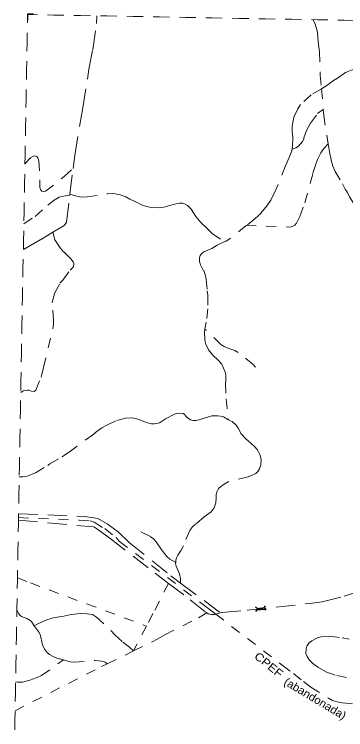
# Model space of a CAD drawing. Extents: x 783.4 to 809.8, y 7536.4 to 7564.6.
# Drawn here: x 783.82 to 787.12, y 7557.44 to 7564.59 of the extents above; entities that cross this region are included whole.
import ezdxf
from ezdxf.enums import TextEntityAlignment as Align

# ---------------------------------------------------------------- set-up
doc = ezdxf.new("R2010")
doc.units = 0
doc.header["$LTSCALE"] = 0.032
for name, pattern in [('DOTTED', [1.5, 0.3, -1.2]), ('LONG_DASHED', [7.5, 6, -1.5]), ('MEDIUM_DASHED', [4.5, 3, -1.5]), ('SHORT_DASHED', [2.7, 1.5, -1.2])]:
    doc.linetypes.add(name, pattern=pattern)
for name, color, linetype, lineweight in [('10', 7, 'Continuous', 25), ('18', 7, 'DOTTED', 13), ('35', 7, 'SHORT_DASHED', 13), ('5', 7, 'LONG_DASHED', 13), ('6', 7, 'MEDIUM_DASHED', 13), ('63', 7, 'Continuous', 25), ('7', 7, 'DOTTED', 13)]:
    doc.layers.add(name, color=color, linetype=linetype, lineweight=lineweight)
doc.layers.add('61', color=7, linetype='Continuous')

msp = doc.modelspace()

# ---------------------------------------------------------------- linework, layer by layer
at = {"layer": '10'}
for p, q in [((786.2398, 7558.6539), (786.2243, 7558.6664)), ((786.2293, 7558.6224), (786.2416, 7558.638)), ((786.2416, 7558.638), (786.3151, 7558.6464)), ((786.3308, 7558.634), (786.3151, 7558.6464))]:
    msp.add_line(p, q, dxfattribs=at)
msp.add_lwpolyline([(786.2398, 7558.6539), (786.3133, 7558.6623), (786.3258, 7558.6779)], dxfattribs=at)
at = {"layer": '18'}
for points in [[(783.8574, 7559.56), (784.463, 7559.5355), (784.5715, 7559.528), (784.6117, 7559.5148), (784.7183, 7559.4507), (784.8325, 7559.3604), (784.8676, 7559.3228), (785.7496, 7558.6555), (785.8274, 7558.5958)], [(785.8274, 7558.5958), (786.4912, 7558.086), (786.6044, 7558.0024), (786.7026, 7557.9216), (786.7781, 7557.8648), (786.9545, 7557.7548), (786.9946, 7557.7341), (787.0407, 7557.7191), (787.0948, 7557.7088), (787.2035, 7557.6979)], [(787.1334, 7557.962), (787.0201, 7557.9846), (786.9229, 7558.0221), (786.8462, 7558.0649), (786.7971, 7558.1043), (786.7641, 7558.1353), (786.74, 7558.172), (786.728, 7558.203), (786.73, 7558.249), (786.737, 7558.2772), (786.758, 7558.3054), (786.7861, 7558.3308), (786.8427, 7558.3594), (786.8788, 7558.3679), (786.9639, 7558.3745), (787.0882, 7558.3594), (787.1604, 7558.3472)]]:
    msp.add_lwpolyline(points, dxfattribs=at)
at = {"layer": '35'}
for points in [[(783.8156, 7557.2399), (783.8207, 7557.5225), (783.8258, 7557.8051), (783.8309, 7558.0877), (783.836, 7558.3703), (783.8411, 7558.6529), (783.8462, 7558.9355), (783.8513, 7559.2181), (783.8563, 7559.5007), (783.8614, 7559.7833), (783.8665, 7560.0659), (783.8716, 7560.3486), (783.8767, 7560.6312), (783.8818, 7560.9138), (783.8869, 7561.1964), (783.892, 7561.479), (783.8971, 7561.7616), (783.9022, 7562.0442), (783.9073, 7562.3268), (783.9124, 7562.6094), (783.9175, 7562.892), (783.9226, 7563.1746), (783.9276, 7563.4572), (783.9327, 7563.7398), (783.9378, 7564.0224), (783.9429, 7564.305), (783.948, 7564.5876)], [(783.948, 7564.5876), (784.2116, 7564.5828), (784.4751, 7564.5781), (784.7386, 7564.5734), (785.0022, 7564.5686), (785.2658, 7564.5638), (785.5293, 7564.5591), (785.7928, 7564.5543), (786.0564, 7564.5495), (786.32, 7564.5448), (786.5835, 7564.54), (786.8471, 7564.5352), (787.1106, 7564.5304), (787.3742, 7564.5256)]]:
    msp.add_lwpolyline(points, dxfattribs=at)
at = {"layer": '5'}
for p, q in [((784.3707, 7562.7919), (784.4023, 7563.0493)), ((784.369, 7562.7827), (784.3707, 7562.7919)), ((785.4768, 7558.9053), (785.8748, 7558.6082)), ((785.8274, 7558.5958), (785.8748, 7558.6082))]:
    msp.add_line(p, q, dxfattribs=at)
for points in [[(784.4023, 7563.0493), (784.4186, 7563.1803), (784.5004, 7563.6546), (784.5611, 7564.0414), (784.5988, 7564.2362), (784.6364, 7564.4979), (784.6384, 7564.5752)], [(784.1997, 7562.412), (784.3142, 7562.4811), (784.3282, 7562.4962), (784.3352, 7562.5112), (784.369, 7562.7827)], [(783.9057, 7562.2394), (784.0761, 7562.3374), (784.1997, 7562.412)], [(783.8581, 7559.5989), (784.5147, 7559.572), (784.5909, 7559.5622), (784.6454, 7559.5517), (784.6746, 7559.5398), (784.7422, 7559.4968), (784.8512, 7559.4169), (784.964, 7559.3105), (785.3785, 7558.9787), (785.4768, 7558.9053)], [(783.8569, 7559.5339), (784.6038, 7559.4683), (784.6165, 7559.4636), (784.7709, 7559.3546), (785.2212, 7559.0049), (785.3553, 7558.9033)], [(785.3553, 7558.9033), (785.5704, 7558.7404), (785.7261, 7558.6159), (785.7388, 7558.6078)], [(785.8748, 7558.6082), (785.8857, 7558.6111), (786.1407, 7558.6346), (786.7687, 7558.7026), (786.8889, 7558.7205), (787.1099, 7558.7755), (787.2861, 7558.8329)], [(785.7388, 7558.6078), (785.7524, 7558.5992), (785.7838, 7558.5912), (785.8101, 7558.5912), (785.8274, 7558.5958)]]:
    msp.add_lwpolyline(points, dxfattribs=at)
at = {"layer": '6'}
for p, q in [((786.8831, 7563.8462), (786.9014, 7563.6374)), ((784.742, 7558.0992), (785.0057, 7558.2287))]:
    msp.add_line(p, q, dxfattribs=at)
for points in [[(786.8013, 7564.536), (786.8203, 7564.4916), (786.8426, 7564.4125), (786.849, 7564.314), (786.8649, 7564.214), (786.8713, 7563.9812), (786.8831, 7563.8462)], [(786.9014, 7563.6374), (786.9064, 7563.5801), (786.9495, 7563.2966)], [(786.9495, 7563.2966), (786.9617, 7563.2165), (786.9817, 7563.1205), (786.995, 7563.0718), (787.0184, 7563.02), (787.0928, 7562.8966), (787.1192, 7562.843), (787.144, 7562.8086), (787.1632, 7562.767), (787.2024, 7562.7038), (787.324, 7562.4822), (787.4856, 7562.2054), (787.5128, 7562.1486), (787.583, 7561.9574), (787.609, 7561.8711), (787.6365, 7561.7914)], [(783.88, 7560.8119), (783.9044, 7560.8263), (783.9423, 7560.8343), (783.9594, 7560.8336), (783.988, 7560.8227), (784.0143, 7560.8213), (784.0321, 7560.835), (784.0832, 7560.9649), (784.1086, 7561.0613), (784.199, 7561.4477), (784.2054, 7561.4917), (784.2062, 7561.5349), (784.1942, 7561.7078), (784.2054, 7561.763), (784.2198, 7561.8054), (784.2718, 7561.9022), (784.2998, 7561.9342), (784.3728, 7562.0344), (784.4019, 7562.0627), (784.4099, 7562.0853), (784.4099, 7562.0984), (784.4019, 7562.1163), (784.3808, 7562.1455), (784.3076, 7562.2161), (784.2735, 7562.2565), (784.2188, 7562.3356), (784.1997, 7562.412)], [(785.0057, 7558.2287), (785.2479, 7558.3477), (785.3204, 7558.3904), (785.6548, 7558.5575), (785.7388, 7558.6078)], [(783.8227, 7557.6313), (784.6867, 7558.072), (784.742, 7558.0992)]]:
    msp.add_lwpolyline(points, dxfattribs=at)
at = {"layer": '63'}
msp.add_lwpolyline([(784.0079, 7564.5899), (783.9463, 7564.5899), (783.9463, 7564.5292)], dxfattribs=at)
at = {"layer": '7'}
msp.add_line((785.1349, 7558.4763), (785.0057, 7558.2287), dxfattribs=at)
for points in [[(787.6817, 7563.7279), (787.657, 7563.742), (787.5439, 7563.7739), (787.4766, 7563.8071), (787.4468, 7563.8311), (787.4274, 7563.8513), (787.4114, 7563.8747), (787.3961, 7563.9092), (787.383, 7563.9716), (787.367, 7564.0126), (787.3351, 7564.0458), (787.3219, 7564.0516), (787.2851, 7564.0555), (787.1887, 7564.0347), (787.1225, 7564.0084), (787.0448, 7563.9531), (787.0031, 7563.9286), (786.9359, 7563.8782), (786.8831, 7563.8462)], [(786.8831, 7563.8462), (786.7817, 7563.7846), (786.6751, 7563.6896), (786.6469, 7563.6458), (786.6061, 7563.5616), (786.5898, 7563.4726), (786.5895, 7563.4152), (786.5969, 7563.3644), (786.5947, 7563.267), (786.5901, 7563.2433)], [(786.5901, 7563.2433), (786.6266, 7563.2542), (786.6526, 7563.2716), (786.6951, 7563.3198), (786.7055, 7563.343), (786.7071, 7563.355), (786.7335, 7563.4286), (786.7727, 7563.5022), (786.8443, 7563.5977), (786.8673, 7563.6164), (786.9014, 7563.6374)], [(786.1324, 7562.4779), (786.5616, 7562.4639), (786.583, 7562.466), (786.6172, 7562.484), (786.6354, 7562.502), (786.6675, 7562.5692), (786.7156, 7562.7065), (786.7983, 7563.0041), (786.8265, 7563.0932), (786.8443, 7563.1391), (786.8759, 7563.2062), (786.9063, 7563.2501), (786.9495, 7563.2966)], [(786.5901, 7563.2433), (786.5865, 7563.2246), (786.5617, 7563.1602), (786.5224, 7563.0768), (786.4223, 7562.823), (786.3775, 7562.7342), (786.3423, 7562.6798), (786.2767, 7562.5998), (786.2215, 7562.5486), (786.1324, 7562.4779)], [(783.9212, 7563.0955), (783.9782, 7563.1568), (784.0138, 7563.1766), (784.0416, 7563.168), (784.0495, 7563.1568), (784.0613, 7563.1259), (784.0706, 7562.9342), (784.0693, 7562.8587), (784.0798, 7562.8327), (784.0891, 7562.8241), (784.1102, 7562.8191), (784.1286, 7562.8216), (784.3134, 7562.97), (784.4023, 7563.0493)], [(783.9104, 7562.4975), (784.0231, 7562.5692), (784.1498, 7562.6843), (784.2131, 7562.7325), (784.2619, 7562.761), (784.322, 7562.7762), (784.369, 7562.7827)], [(784.3707, 7562.7919), (784.4282, 7562.7758), (784.4823, 7562.7635), (784.543, 7562.7647), (784.7503, 7562.7966), (784.7959, 7562.7998), (784.8215, 7562.7974), (784.8727, 7562.7862), (784.9287, 7562.7654), (784.9695, 7562.7422), (785.0431, 7562.7094), (785.0871, 7562.6862), (785.1345, 7562.6682), (785.1855, 7562.6582), (785.2687, 7562.655), (785.3207, 7562.6646), (785.4015, 7562.6886), (785.4647, 7562.703), (785.4967, 7562.7022), (785.5167, 7562.6966), (785.5447, 7562.679), (785.5807, 7562.6414), (785.6271, 7562.5678), (785.6767, 7562.5094), (785.7367, 7562.4542), (785.7911, 7562.3998), (785.912, 7562.3156)], [(786.1324, 7562.4779), (785.9761, 7562.3539), (785.9308, 7562.3246), (785.912, 7562.3156)], [(785.912, 7562.3156), (785.8425, 7562.2822), (785.7888, 7562.2512), (785.7086, 7562.2158), (785.6834, 7562.1977), (785.6716, 7562.1782), (785.6656, 7562.1573), (785.6649, 7562.1191), (785.6745, 7562.0878), (785.7031, 7562.0334), (785.7079, 7562.0294), (785.7204, 7561.9909), (785.7308, 7561.9422), (785.7415, 7561.827), (785.7495, 7561.783), (785.7495, 7561.6478), (785.7327, 7561.5125), (785.7198, 7561.4445)], [(785.7198, 7561.4445), (785.7156, 7561.4222), (785.7186, 7561.3332), (785.729, 7561.2942), (785.7557, 7561.2372), (785.794, 7561.1868), (785.8543, 7561.1301), (785.8871, 7561.0925), (785.9207, 7561.0149), (785.9271, 7560.9869), (785.9287, 7560.9205), (785.9255, 7560.9037), (785.9303, 7560.7458), (785.9547, 7560.5392)], [(786.2245, 7561.0651), (786.2019, 7561.0909), (786.0518, 7561.2094), (786.0168, 7561.2317), (785.9592, 7561.2493), (785.9117, 7561.2704), (785.8791, 7561.2915), (785.7198, 7561.4445)], [(783.8647, 7559.9672), (783.9015, 7559.9686), (783.943, 7559.9755), (784.0275, 7560.0096), (784.1502, 7560.0821), (784.171, 7560.0989), (784.2926, 7560.1693), (784.351, 7560.2093), (784.3631, 7560.2141), (784.5983, 7560.3885), (784.6415, 7560.4253), (784.6887, 7560.4581), (784.7399, 7560.4853), (784.8407, 7560.5309), (784.9271, 7560.5549), (784.9943, 7560.5581), (785.0623, 7560.5421), (785.1335, 7560.5101), (785.1863, 7560.4981), (785.2167, 7560.4965), (785.2671, 7560.5077), (785.3271, 7560.5485), (785.4151, 7560.5957), (785.4471, 7560.6045), (785.5055, 7560.6005), (785.5415, 7560.5613), (785.5743, 7560.5373), (785.6023, 7560.5301), (785.6279, 7560.5293), (785.6607, 7560.5373), (785.7127, 7560.5557), (785.7895, 7560.5765), (785.8487, 7560.5789), (785.8743, 7560.5757), (785.9055, 7560.5661), (785.9487, 7560.5421), (785.9547, 7560.5392)], [(785.9547, 7560.5392), (785.9753, 7560.5291), (785.9897, 7560.521), (786.0305, 7560.4841), (786.0535, 7560.45), (786.0767, 7560.4013), (786.1295, 7560.3453), (786.1519, 7560.3293), (786.2111, 7560.2749), (786.2431, 7560.2381), (786.2679, 7560.1925), (786.2807, 7560.1397), (786.2776, 7560.0884), (786.2636, 7560.0493), (786.2477, 7560.0218), (786.2262, 7560.0023), (786.152, 7559.9669), (785.9509, 7559.9196), (785.9113, 7559.8963), (785.8749, 7559.8692), (785.8564, 7559.8504), (785.8411, 7559.8252), (785.8322, 7559.7911), (785.8329, 7559.7577), (785.8285, 7559.7083), (785.8129, 7559.6589), (785.7825, 7559.6172), (785.711, 7559.5668), (785.6271, 7559.4973), (785.5919, 7559.4637), (785.5679, 7559.4333), (785.5039, 7559.2797), (785.4807, 7559.2357), (785.4487, 7559.1861), (785.4359, 7559.1589), (785.4295, 7559.1365), (785.4278, 7559.1132)], [(785.0806, 7559.4193), (785.1737, 7559.3725), (785.2054, 7559.3491), (785.2335, 7559.3197), (785.2911, 7559.2309), (785.3383, 7559.1733), (785.3687, 7559.1445), (785.4278, 7559.1132)], [(785.4278, 7559.1132), (785.427, 7559.1024), (785.4322, 7559.0739), (785.4649, 7558.9995), (785.4752, 7558.9515), (785.4768, 7558.9053)], [(783.8466, 7558.9575), (783.9756, 7558.9085), (785.1349, 7558.4763)], [(785.3553, 7558.9033), (785.2005, 7558.602), (785.1349, 7558.4763)], [(783.8408, 7558.6377), (783.8561, 7558.6066), (783.8705, 7558.5858), (783.8888, 7558.5724), (783.9417, 7558.5515), (783.973, 7558.5326), (783.9861, 7558.5209), (784.0151, 7558.48)], [(784.0151, 7558.48), (784.0573, 7558.5027), (784.1402, 7558.5375), (784.216, 7558.563), (784.2947, 7558.5737), (784.3847, 7558.5938), (784.4805, 7558.6018), (784.542, 7558.6005), (784.5963, 7558.5925), (784.6378, 7558.567), (784.7791, 7558.4332), (784.8183, 7558.3884), (784.9007, 7558.3164), (784.9647, 7558.2652), (785.0057, 7558.2287)], [(784.0151, 7558.48), (784.0638, 7558.4114), (784.0772, 7558.3811), (784.0928, 7558.3022), (784.1033, 7558.271), (784.1196, 7558.241), (784.1405, 7558.2159), (784.1679, 7558.1939), (784.2048, 7558.1728), (784.2407, 7558.1575), (784.307, 7558.1378)], [(783.8279, 7557.9206), (783.8454, 7557.9176), (783.8972, 7557.9168), (783.9721, 7557.9348), (784.0446, 7557.9624), (784.0876, 7557.9826), (784.307, 7558.1378)], [(784.307, 7558.1378), (784.3745, 7558.1177), (784.413, 7558.1147), (784.6216, 7558.1327), (784.6894, 7558.1266), (784.7221, 7558.1156), (784.742, 7558.0992)]]:
    msp.add_lwpolyline(points, dxfattribs=at)

# ---------------------------------------------------------------- texts
at = {"layer": '61'}
for s, rotation, width, p in [('CPEF', 321, 1.15, (786.3317, 7558.0588)), ('(abandonada)', 329, 1.05, (786.7997, 7557.7183))]:
    msp.add_text(s, height=0.08, rotation=rotation, dxfattribs=dict(at, width=width)).set_placement(p, align=Align.CENTER)

doc.saveas('drawing.dxf')
